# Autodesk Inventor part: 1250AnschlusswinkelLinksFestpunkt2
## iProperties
Category: PARTsolutions
Created: 2011-08
Part Number: 1250AnschlusswinkelLinksFestpunkt2
Catalog Web Link: www.cadenas.de
Description: 1250 Anschlusswinkel links Festpunkt - Anschlusswinkel links Festpunkt
Document SubType Name: Modeling
Designer: PARTsolutions
Density: 1 g/cm^3
NB: 1250AnschlusswinkelLinksFestpunkt2
NN: 1250 Anschlusswinkel links Festpunkt
NT: Anschlusswinkel links Festpunkt
NBSYN: 1250AnschlusswinkelLinksFestpunkt2
LINA: 1250AnschlusswinkelLinksFestpunkt2
BEST: 1250AnschlusswinkelLinksFestpunkt
FA: 2
B: 0.000
KT: DUMMY
SUPPLIER: Kabelschlepp
ARTICLENO: 1250AnschlusswinkelLinksFestpunkt2
BOMINFO: 1250AnschlusswinkelLinksFestpunkt2
CREATOR: CADENAS GmbH
PSOL_IDENT_0: {\\10.0.0.251\ps_data\23d-libs\kabelschlepp\4_eketten_st\parts\1250_anschlusswinkel_links_f.prj},242
PSOL_IDENT_1: {VTYP=3D},{NB=1250AnschlusswinkelLinksFestpunkt2},{LINA=1250AnschlusswinkelLinksFestpunkt2},{NN=125
PSOL_IDENT_2: 0 Anschlusswinkel links Festpunkt},{DATE=08.06.2007 12:30:25},{GEOMDATE=13.03.2007 11:12:00},{VERSIO
PSOL_IDENT_3: N=},{LINEID=10},{LINESUBID=-1},{WBVAR=FA}  {NB=1250AnschlusswinkelLinksFestpunkt2},{LINA=1250Anschlu
PSOL_IDENT_4: sswinkelLinksFestpunkt2},{KT=DUMMY},{BEST=1250AnschlusswinkelLinksFestpunkt},{FA=2},{B=0}
Title: 1250AnschlusswinkelLinksFestpunkt2
Author: Cadenas PARTsolutions
Comments: Anschlusswinkel links Festpunkt
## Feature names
1. Extrusion1
2. Extrusion2
3. Extrusion3
4. Extrusion4
5. Extrusion5
6. Revolution1
7. Revolution2
8. Extrusion6
